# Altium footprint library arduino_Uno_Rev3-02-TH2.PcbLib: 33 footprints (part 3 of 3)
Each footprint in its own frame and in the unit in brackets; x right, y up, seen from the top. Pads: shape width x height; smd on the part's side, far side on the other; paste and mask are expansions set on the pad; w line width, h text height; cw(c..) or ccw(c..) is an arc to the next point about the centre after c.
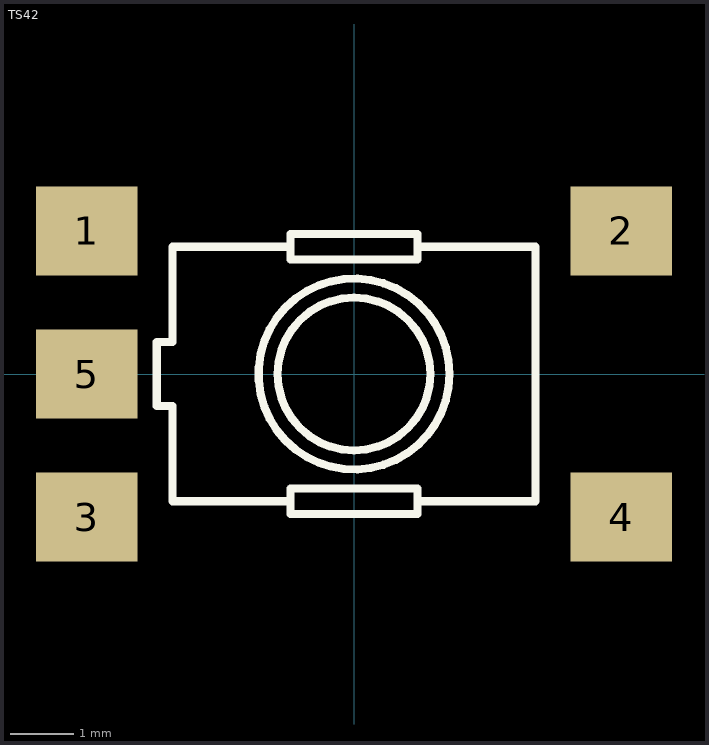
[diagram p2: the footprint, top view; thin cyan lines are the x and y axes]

## TS42 [mm]
pads (5):
  rect 1.6x1.4 smd: 1(-4.2,2.25) 2(4.2,2.25) 3(-4.2,-2.25) 4(4.2,-2.25) 5(-4.2,0)
Top Layer:
  rectangle: -4.699,-0.381 -3.81,0.381
Top Overlay:
  circle w0.127: c0,0 r1.5
  circle w0.127: c0,0 r1.2
  lines w0.127: -1,-2 -1,-1.8 1,-1.8 1,-2 ; -1,-2 -1,-2.2 1,-2.2 1,-2 ; -1,-2 -2.85,-2 -2.85,-0.5 -3.1,-0.5 -3.1,0.5 -2.85,0.5 -2.85,2 -1,2 ; -1,2 -1,2.2 1,2.2 1,2 ; -1,2 -1,1.8 1,1.8 1,2 ; 1,-2 2.85,-2 2.85,2 1,2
